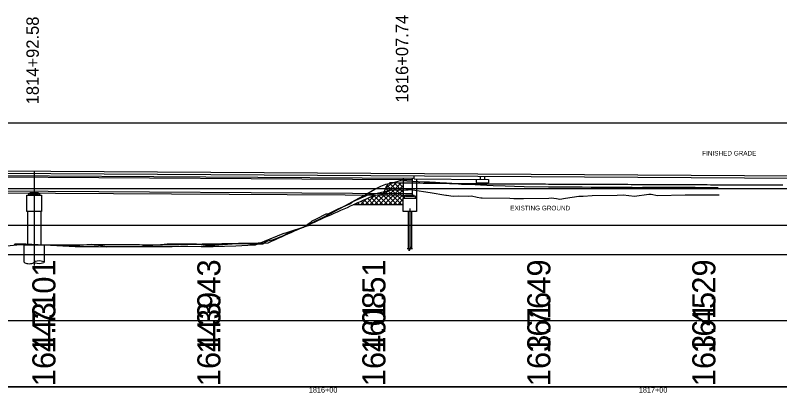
# Model space of a CAD drawing. Extents: x 2126510 to 2136144, y 865066 to 868066.
# Drawn here: x 2134109.8 to 2134341.5, y 867812.5 to 867927 of the extents above; entities that cross this region are included whole.
import ezdxf

# ---------------------------------------------------------------- set-up
doc = ezdxf.new("R2010")
doc.units = 0
for name, color, linetype in [('RD_DTM_BkLn1', 7, 'Continuous'), ('RD_EX_Bldg', 7, 'Continuous'), ('RD_EX_Bridge', 7, 'Continuous'), ('RD_EX_Conc_Curb', 7, 'Continuous'), ('RD_EX_DR_Pipe', 7, 'Continuous'), ('RD_EX_GuardRail', 7, 'Continuous'), ('RD_EX_H2O', 7, 'Continuous'), ('RD_EX_Misc', 7, 'Continuous'), ('RD_EX_Misc_Golf_Cartpath', 7, 'Continuous'), ('RD_EX_UT', 7, 'Continuous'), ('RD_HC_Data', 7, 'Continuous'), ('RD_HC_txCode', 7, 'Continuous')]:
    doc.layers.add(name, color=color, linetype=linetype)

msp = doc.modelspace()

# ---------------------------------------------------------------- linework, layer by layer
at = {"layer": 'RD_DTM_BkLn1'}
for p, q in [((2133649.16, 867881.28), (2134230.74, 867877.62)), ((2134230.74, 867877.35), (2134230.74, 867878.35)), ((2134250.74, 867878.22), (2134250.74, 867877.22)), ((2134251.99, 867878.22), (2134251.99, 867877.22)), ((2134230.74, 867877.35), (2134253.24, 867877.2)), ((2134249.49, 867877.23), (2134249.49, 867876.23)), ((2134249.49, 867876.23), (2134253.24, 867876.2)), ((2134253.24, 867877.2), (2134253.24, 867876.2)), ((2134117.32, 867872.8), (2134113.82, 867872.8)), ((2134113.82, 867872.8), (2134113.82, 867872.47)), ((2134116.9, 867873.09), (2134114.24, 867873.09)), ((2134114.24, 867872.8), (2134116.9, 867872.8)), ((2134117.32, 867872.47), (2134117.32, 867872.8)), ((2134231.15, 867872.08), (2134227.65, 867872.08)), ((2134227.65, 867872.08), (2134227.65, 867871.51)), ((2134230.74, 867872.37), (2134228.07, 867872.37)), ((2134228.07, 867872.37), (2134228.07, 867872.08)), ((2134228.07, 867872.08), (2134230.74, 867872.08)), ((2134230.74, 867872.08), (2134230.74, 867872.37)), ((2134231.15, 867871.51), (2134231.15, 867872.08)), ((2134113.57, 867867.47), (2134113.57, 867857.35)), ((2134117.57, 867867.47), (2134117.57, 867857.35))]:
    msp.add_line(p, q, dxfattribs=at)
for points in [[(2134113.32, 867872.47), (2134117.82, 867872.47), (2134117.82, 867867.47), (2134113.32, 867867.47)], [(2134227.4, 867871.51), (2134231.4, 867871.51), (2134231.4, 867867.51), (2134227.4, 867867.51)]]:
    msp.add_lwpolyline(points, close=True, dxfattribs=at)
msp.add_lwpolyline([(2134112.57, 867852.11), (2134112.57, 867857.35), (2134118.57, 867857.35), (2134118.57, 867852.11)], dxfattribs=at)
msp.add_ellipse((2134117.07, 867852.11), major_axis=(-1.5, 0), ratio=0.310397, dxfattribs=at)
msp.add_ellipse((2134114.07, 867852.11), major_axis=(-1.5, 0), ratio=0.310397, start_param=0, end_param=3.141593, dxfattribs=at)
at = {"layer": 'RD_EX_Bldg'}
for p, q in [((2134228.9, 867867.51), (2134228.9, 867856.15)), ((2134229.9, 867867.51), (2134229.9, 867856.15))]:
    msp.add_line(p, q, dxfattribs=at)
msp.add_lwpolyline([(2134230.2, 867856.15), (2134229.66, 867856.15), (2134229.66, 867856.73), (2134229.15, 867855.57), (2134229.15, 867856.15), (2134228.61, 867856.15)], dxfattribs=at)
at = {"layer": 'RD_EX_Bridge'}
for p, q in [((2134114.24, 867873.09), (2134114.24, 867872.8)), ((2134116.9, 867872.8), (2134116.9, 867873.09))]:
    msp.add_line(p, q, dxfattribs=at)
at = {"layer": 'RD_EX_Conc_Curb'}
msp.add_lwpolyline([(2134109.81, 867857.64), (2134112.51, 867857.67), (2134112.77, 867857.67), (2134113.08, 867857.66), (2134127.99, 867856.87), (2134129.97, 867856.84), (2134132.29, 867856.82), (2134135.1, 867856.83), (2134137.49, 867856.77), (2134140.01, 867856.82), (2134151.71, 867856.82), (2134154.86, 867856.83), (2134157.34, 867856.9), (2134159.92, 867856.95), (2134160.3, 867856.95), (2134162.13, 867857), (2134166.15, 867856.84), (2134166.57, 867856.83), (2134166.67, 867856.83), (2134169.77, 867856.87), (2134176.63, 867857.04), (2134182.15, 867857.32), (2134182.54, 867857.33), (2134182.63, 867857.36), (2134185.32, 867858.46), (2134191.04, 867860.76), (2134191.35, 867860.9), (2134191.87, 867861.03), (2134198.56, 867863.25), (2134199.5, 867863.89), (2134203.23, 867865.78), (2134209.94, 867869.27), (2134213.92, 867871.5), (2134215.62, 867872.48), (2134218.8, 867874.27), (2134220.62, 867875.16), (2134222.16, 867875.73), (2134224.28, 867876.22), (2134226.45, 867876.83), (2134226.53, 867876.9), (2134226.77, 867876.89), (2134230.24, 867876.7), (2134233.74, 867876.51), (2134235.4, 867876.46), (2134237.17, 867876.33), (2134239.8, 867876.19), (2134240.52, 867876.16), (2134243.82, 867875.98), (2134244.12, 867875.86), (2134245.05, 867875.81), (2134247.6, 867875.75), (2134250.81, 867875.58), (2134254.69, 867875.36), (2134258.3, 867875.24), (2134261.1, 867875.17), (2134264, 867875.11), (2134271.39, 867875), (2134272.38, 867874.99), (2134280.61, 867874.92), (2134281.67, 867874.91), (2134284.39, 867874.87), (2134288.43, 867874.87), (2134290.27, 867874.82), (2134291.96, 867874.82), (2134296.7, 867874.82), (2134296.97, 867874.77), (2134299.93, 867874.82), (2134302.25, 867874.82), (2134307.53, 867874.82), (2134311.52, 867874.82), (2134312.15, 867874.82), (2134312.54, 867874.82), (2134315.92, 867874.81), (2134322.82, 867874.78)], dxfattribs=at)
at = {"layer": 'RD_EX_DR_Pipe'}
for p, q in [((2134218.67, 867869.51), (2134225.39, 867876.23)), ((2134220.08, 867869.51), (2134226.79, 867876.21)), ((2134222.06, 867874.31), (2134224, 867876.25)), ((2134223.27, 867876.07), (2134227.4, 867871.94)), ((2134224.51, 867876.24), (2134227.4, 867873.35)), ((2134225.95, 867876.22), (2134227.4, 867874.76)), ((2134227.38, 867876.2), (2134227.4, 867876.18)), ((2134221.5, 867869.51), (2134227.4, 867875.41)), ((2134222.1, 867874.41), (2134227.01, 867869.51)), ((2134222.52, 867875.4), (2134227.4, 867870.52)), ((2134222.91, 867869.51), (2134227.4, 867874)), ((2134214.43, 867869.51), (2134216.25, 867871.33)), ((2134215.84, 867869.51), (2134218.71, 867872.38)), ((2134216.56, 867871.47), (2134218.52, 867869.51)), ((2134217.25, 867869.51), (2134220.35, 867872.6)), ((2134217.53, 867871.91), (2134219.93, 867869.51)), ((2134218.51, 867872.34), (2134221.35, 867869.51)), ((2134219.74, 867872.53), (2134222.76, 867869.51)), ((2134220.97, 867872.71), (2134224.18, 867869.51)), ((2134221.7, 867873.4), (2134225.59, 867869.51)), ((2134224.32, 867869.51), (2134227.4, 867872.59)), ((2134225.74, 867869.51), (2134227.4, 867871.17)), ((2134212.66, 867869.71), (2134212.86, 867869.51)), ((2134213.01, 867869.51), (2134213.67, 867870.16)), ((2134213.64, 867870.15), (2134214.28, 867869.51)), ((2134214.61, 867870.59), (2134215.69, 867869.51)), ((2134215.58, 867871.03), (2134217.11, 867869.51)), ((2134227.15, 867869.51), (2134227.4, 867869.76))]:
    msp.add_line(p, q, dxfattribs=at)
msp.add_lwpolyline([(2134227.4, 867869.51), (2134212.2, 867869.51)], dxfattribs=at)
at = {"layer": 'RD_EX_GuardRail'}
for p, q in [((2135251.98, 867894.32), (2130671.73, 867894.32)), ((2135251.98, 867874.32), (2133154.4, 867874.32)), ((2135251.98, 867854.32), (2130671.73, 867854.32)), ((2135251.98, 867834.32), (2130671.73, 867834.32)), ((2135251.98, 867814.32), (2130671.73, 867814.32))]:
    msp.add_line(p, q, dxfattribs=at)
at = {"layer": 'RD_EX_H2O'}
for points in [[(2134186.47, 867857.97), (2134187.47, 867858.46), (2134188.47, 867858.92), (2134189.47, 867859.36), (2134190.47, 867859.81), (2134191.47, 867860.26), (2134192.47, 867860.7), (2134193.47, 867861.15), (2134194.47, 867861.59), (2134195.47, 867862.04), (2134196.47, 867862.49), (2134197.47, 867862.93), (2134198.47, 867863.38), (2134199.47, 867863.83), (2134200.47, 867864.27), (2134201.47, 867864.72), (2134202.47, 867865.16), (2134203.47, 867865.61), (2134204.47, 867866.06), (2134205.47, 867866.5), (2134206.47, 867866.95), (2134207.47, 867867.4), (2134208.47, 867867.84), (2134209.47, 867868.29), (2134210.47, 867868.73), (2134211.47, 867869.18), (2134212.47, 867869.63), (2134213.47, 867870.07), (2134214.47, 867870.52), (2134215.47, 867870.98), (2134216.47, 867871.43), (2134217.47, 867871.88), (2134218.47, 867872.34), (2134219.47, 867872.5), (2134220.47, 867872.62), (2134221.47, 867872.81), (2134222.47, 867875.35), (2134223.47, 867876.26), (2134224.47, 867876.24), (2134225.47, 867876.23), (2134226.47, 867876.22), (2134227.47, 867876.2), (2134228.47, 867876.19), (2134229.47, 867876.17), (2134230.47, 867876.16), (2134231.47, 867876.15), (2134232.47, 867876.13), (2134233.47, 867876.12), (2134234.47, 867876.11), (2134235.47, 867876.1), (2134236.47, 867876.08), (2134237.47, 867876.07), (2134238.47, 867876.06), (2134239.47, 867876.05), (2134240.47, 867876.03), (2134241.47, 867876.02), (2134242.47, 867876.01), (2134243.47, 867876), (2134244.47, 867875.98), (2134245.47, 867875.97), (2134246.47, 867875.96), (2134247.47, 867875.95), (2134248.47, 867875.93), (2134249.47, 867875.92), (2134250.47, 867875.91), (2134251.47, 867875.9), (2134252.47, 867875.89), (2134253.47, 867875.89), (2134254.47, 867875.89), (2134255.47, 867875.89), (2134256.47, 867875.88), (2134257.47, 867875.88), (2134258.47, 867875.88), (2134259.47, 867875.87), (2134260.47, 867875.87), (2134261.47, 867875.87), (2134262.47, 867875.87), (2134263.47, 867875.86), (2134264.47, 867875.86), (2134265.47, 867875.85), (2134266.47, 867875.85), (2134267.47, 867875.84), (2134268.47, 867875.83), (2134269.47, 867875.83), (2134270.47, 867875.82), (2134271.47, 867875.81), (2134272.47, 867875.81), (2134273.47, 867875.81), (2134274.47, 867875.8), (2134275.47, 867875.8), (2134276.47, 867875.79), (2134277.47, 867875.79), (2134278.47, 867875.79), (2134279.47, 867875.78), (2134280.47, 867875.78), (2134281.47, 867875.77), (2134282.47, 867875.77), (2134283.47, 867875.76), (2134284.47, 867875.76), (2134285.47, 867875.76), (2134286.47, 867875.75)], [(2134286.47, 867875.75), (2134287.47, 867875.75), (2134288.47, 867875.74), (2134289.47, 867875.74), (2134290.47, 867875.74), (2134291.47, 867875.73), (2134292.47, 867875.73), (2134293.47, 867875.72), (2134294.47, 867875.72), (2134295.47, 867875.72), (2134296.47, 867875.71), (2134297.47, 867875.71), (2134298.47, 867875.7), (2134299.47, 867875.7), (2134300.47, 867875.69), (2134301.47, 867875.69), (2134302.47, 867875.69), (2134303.47, 867875.68), (2134304.47, 867875.68), (2134305.47, 867875.67), (2134306.47, 867875.67), (2134307.47, 867875.66), (2134308.47, 867875.66), (2134309.47, 867875.65), (2134310.47, 867875.65), (2134311.47, 867875.64), (2134312.47, 867875.64), (2134313.47, 867875.63), (2134314.47, 867875.63), (2134315.47, 867875.63), (2134316.47, 867875.62), (2134317.47, 867875.62), (2134318.47, 867875.62), (2134319.47, 867875.62), (2134320.47, 867875.61), (2134321.47, 867875.61), (2134322.47, 867875.61), (2134323.47, 867875.6), (2134324.47, 867875.6), (2134325.47, 867875.6), (2134326.47, 867875.6), (2134327.47, 867875.59), (2134328.47, 867875.59), (2134329.47, 867875.59), (2134330.47, 867875.59), (2134331.47, 867875.58), (2134332.47, 867875.58), (2134333.47, 867875.58), (2134334.47, 867875.58), (2134335.47, 867875.58), (2134336.47, 867875.58), (2134337.47, 867875.58), (2134338.47, 867875.59), (2134339.47, 867875.59), (2134340.47, 867875.59), (2134341.47, 867875.6), (2134342.47, 867875.6)], [(2134109.47, 867857.61), (2134110.47, 867857.55), (2134111.47, 867857.5), (2134112.47, 867857.45), (2134113.47, 867857.39), (2134114.47, 867857.36), (2134115.47, 867857.35), (2134116.47, 867857.35), (2134117.47, 867857.34), (2134118.47, 867857.33), (2134119.47, 867857.33), (2134120.47, 867857.32), (2134121.47, 867857.32), (2134122.47, 867857.33), (2134123.47, 867857.33), (2134124.47, 867857.34), (2134125.47, 867857.35), (2134126.47, 867857.36), (2134127.47, 867857.37), (2134128.47, 867857.37), (2134129.47, 867857.39), (2134130.47, 867857.41), (2134131.47, 867857.42), (2134132.47, 867857.44), (2134133.47, 867857.46), (2134134.47, 867857.46), (2134135.47, 867857.46), (2134136.47, 867857.46), (2134137.47, 867857.46), (2134138.47, 867857.46), (2134139.47, 867857.46), (2134140.47, 867857.45), (2134141.47, 867857.45), (2134142.47, 867857.45), (2134143.47, 867857.45), (2134144.47, 867857.45), (2134145.47, 867857.45), (2134146.47, 867857.44), (2134147.47, 867857.42), (2134148.47, 867857.39), (2134149.47, 867857.37), (2134150.47, 867857.35), (2134151.47, 867857.32), (2134152.47, 867857.35), (2134153.47, 867857.37), (2134154.47, 867857.4), (2134155.47, 867857.43), (2134156.47, 867857.45), (2134157.47, 867857.47), (2134158.47, 867857.49), (2134159.47, 867857.51), (2134160.47, 867857.53), (2134161.47, 867857.54), (2134162.47, 867857.56), (2134163.47, 867857.58), (2134164.47, 867857.59), (2134165.47, 867857.61), (2134166.47, 867857.63), (2134167.47, 867857.65), (2134168.47, 867857.66), (2134169.47, 867857.68), (2134170.47, 867857.7), (2134171.47, 867857.71), (2134172.47, 867857.73), (2134173.47, 867857.75), (2134174.47, 867857.77), (2134175.47, 867857.78), (2134176.47, 867857.8), (2134177.47, 867857.82), (2134178.47, 867857.83), (2134179.47, 867857.85), (2134180.47, 867857.87), (2134181.47, 867857.89), (2134182.47, 867857.9), (2134183.47, 867857.92), (2134184.47, 867857.94), (2134185.47, 867857.89), (2134186.47, 867857.97)]]:
    msp.add_lwpolyline(points, dxfattribs=at)
at = {"layer": 'RD_EX_Misc'}
for p, q in [((2133649.16, 867882.7), (2134667.76, 867876.29)), ((2131523, 867814.32), (2135677.25, 867814.32))]:
    msp.add_line(p, q, dxfattribs=at)
msp.add_lwpolyline([(2131430.13, 867814.32), (2131430.13, 867863.32), (2136143.96, 867863.32)], dxfattribs=at)
at = {"layer": 'RD_EX_Misc_Golf_Cartpath'}
msp.add_lwpolyline([(2134105.04, 867856.85), (2134110.33, 867857.37), (2134112.75, 867857.59), (2134122.79, 867857.27), (2134126.21, 867857.11), (2134127.52, 867857.1), (2134128.33, 867857.12), (2134132.86, 867857.53), (2134133.72, 867857.36), (2134135.08, 867857.23), (2134136.99, 867856.92), (2134139.64, 867856.82), (2134148.22, 867856.99), (2134155, 867857.61), (2134155.9, 867857.71), (2134156.14, 867857.71), (2134163.13, 867857.63), (2134164.73, 867857.65), (2134167.51, 867857.26), (2134170.34, 867857.31), (2134172.84, 867857.47), (2134176.9, 867857.76), (2134180.96, 867857.7), (2134184.83, 867857.7), (2134185.31, 867858.04), (2134186.39, 867858.53), (2134188.34, 867859.09), (2134191.1, 867860.21), (2134192.96, 867861.1), (2134197.15, 867862.76), (2134199.54, 867864.31), (2134199.8, 867864.63), (2134200.91, 867865.11), (2134204.03, 867866.73), (2134204.68, 867866.74), (2134207.71, 867868.26), (2134211.2, 867869.81), (2134212.15, 867870.5), (2134216.96, 867872.62), (2134218.52, 867872.86), (2134218.6, 867872.88), (2134223.57, 867873.96), (2134228.23, 867874.08), (2134228.89, 867874.09), (2134229.95, 867874.13), (2134230.24, 867874.08), (2134235.52, 867873.19), (2134240.27, 867872.45), (2134240.56, 867872.4), (2134242.51, 867872.09), (2134244.29, 867872.18), (2134247.26, 867872.17), (2134248.06, 867872.21), (2134249.79, 867871.84), (2134250.89, 867871.67), (2134251.37, 867871.59), (2134259.74, 867871.53), (2134260.9, 867871.37), (2134261.21, 867871.37), (2134263.89, 867871.38), (2134271.54, 867871.57), (2134272.25, 867871.59), (2134273.85, 867871.4), (2134274.86, 867871.26), (2134276.56, 867871.5), (2134280.61, 867872.15), (2134281.87, 867872.12), (2134281.92, 867872.12), (2134284.7, 867872.34), (2134292.19, 867872.48), (2134294.01, 867872.52), (2134297.48, 867872.17), (2134301.8, 867872.75), (2134302.14, 867872.76), (2134302.52, 867872.7), (2134304.5, 867872.37), (2134312.84, 867872.49), (2134313.72, 867872.51), (2134314.96, 867872.49), (2134315.82, 867872.52), (2134316.87, 867872.53), (2134323.17, 867872.51)], dxfattribs=at)
at = {"layer": 'RD_EX_UT'}
msp.add_line((2133649.16, 867882.01), (2134667.76, 867875.59), dxfattribs=at)
at = {"layer": 'RD_HC_Data'}
for p, q in [((2134115.57, 867879.77), (2134115.57, 867851.1)), ((2134229.4, 867868.43), (2134229.4, 867856.15))]:
    msp.add_line(p, q, dxfattribs=at)
at = {"layer": 'RD_HC_txCode'}
for p, q in [((2133885.65, 867879.37), (2134227.4, 867877.22)), ((2134227.4, 867877.64), (2134227.4, 867871.51)), ((2134227.4, 867877.22), (2134230.07, 867877.2)), ((2134230.07, 867877.64), (2134230.07, 867872.37)), ((2134231.4, 867877.35), (2134231.4, 867871.51)), ((2133885.65, 867875.12), (2134227.4, 867872.97)), ((2133885.65, 867874.54), (2134227.4, 867872.39)), ((2134227.4, 867872.97), (2134230.07, 867872.95)), ((2134227.4, 867872.39), (2134230.07, 867872.37))]:
    msp.add_line(p, q, dxfattribs=at)

# ---------------------------------------------------------------- texts
at = {"layer": 'RD_EX_Misc'}
for s, height, p in [('1816+07.74', 3.75, (2134228.9, 867900.52)), ('1814+92.58', 3.75, (2134116.96, 867899.98)), ('143.01', 7, (2134122, 867824.32)), ('143.43', 7, (2134172, 867824.32)), ('161.51', 7, (2134222, 867824.32)), ('161.49', 7, (2134272, 867824.32)), ('161.29', 7, (2134322, 867824.32)), ('164.71', 7, (2134122, 867814.47)), ('164.39', 7, (2134172, 867814.47)), ('164.08', 7, (2134222, 867814.47)), ('163.76', 7, (2134272, 867814.47)), ('163.45', 7, (2134322, 867814.47))]:
    msp.add_text(s, height=height, rotation=90, dxfattribs=at).set_placement(p)
for s, height, p in [('FINISHED GRADE', 1.4, (2134317.99, 867884.45)), ('EXISTING GROUND', 1.4, (2134259.85, 867867.82)), ('1816+00', 1.6, (2134198.79, 867812.52)), ('1817+00', 1.6, (2134298.79, 867812.52))]:
    msp.add_text(s, height=height, dxfattribs=at).set_placement(p)

doc.saveas('drawing.dxf')
